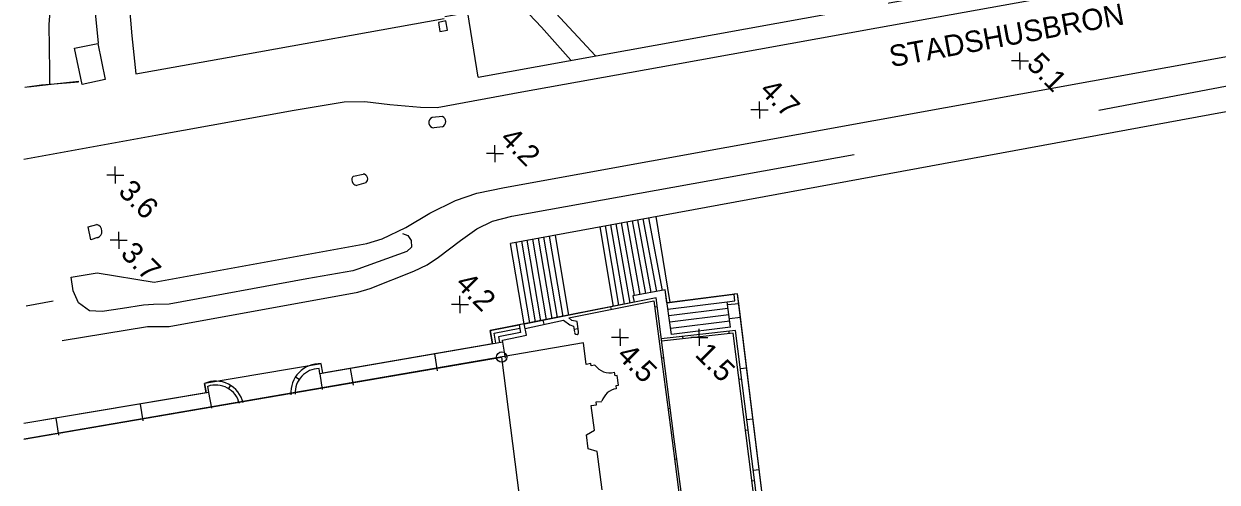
# Model space of a CAD drawing. Extents: x 1596643 to 1597288, y 13057194 to 13057957.
# Drawn here: x 1596648.4 to 1596788, y 13057385.4 to 13057439.2 of the extents above; entities that cross this region are included whole.
import ezdxf

# ---------------------------------------------------------------- set-up
doc = ezdxf.new("R2010")
doc.units = 0
for name, color, linetype in [('BAS bro ej def L', 7, 'Continuous'), ('BAS byggnad anläggning L', 7, 'Continuous'), ('BAS fastighetsgräns samfällighet L', 7, 'Continuous'), ('BAS grind bom låst L', 7, 'Continuous'), ('BAS gränspunkt P', 7, 'Continuous'), ('BAS gång- cykelväg L', 7, 'Continuous'), ('BAS kajkant L', 7, 'Continuous'), ('BAS Level 16', 7, 'Continuous'), ('BAS Level 18', 7, 'Continuous'), ('BAS Level 19', 7, 'Continuous'), ('BAS Level 37', 7, 'Continuous'), ('BAS markytetext T', 7, 'Continuous'), ('BAS trappa L', 7, 'Continuous'), ('BAS väg T', 7, 'Continuous'), ('BAS vägbanekant L', 7, 'Continuous')]:
    doc.layers.add(name, color=color, linetype=linetype)

msp = doc.modelspace()

# ---------------------------------------------------------------- linework, layer by layer
at = {"layer": 'BAS bro ej def L'}
for points in [[(1596701.55, 13057432.92), (1596795.38, 13057449.95), (1596800, 13057453.76)], [(1596705.32, 13057413.45), (1596795.42, 13057430.04)]]:
    msp.add_lwpolyline(points, dxfattribs=at)
at = {"layer": 'BAS byggnad anläggning L'}
for points in [[(1596655.21, 13057432.03), (1596654.31, 13057436.29), (1596657.04, 13057436.86), (1596657.9, 13057432.64), (1596655.21, 13057432.03)], [(1596715.2, 13057399.17), (1596714.76, 13057399.08), (1596714.72, 13057399.34), (1596714.19, 13057399.24), (1596713.86, 13057401.77), (1596648.39, 13057390.49)], [(1596717.71, 13057396.4), (1596717.69, 13057396.78), (1596717.96, 13057396.82), (1596717.82, 13057397.94), (1596717.56, 13057397.9), (1596717.48, 13057398.33)], [(1596716.03, 13057384.55), (1596715.45, 13057389.03), (1596714.4, 13057389.35), (1596714.2, 13057390.98), (1596715.14, 13057391.53), (1596714.78, 13057394.45), (1596715.37, 13057394.51), (1596715.34, 13057394.86), (1596716.01, 13057394.92)]]:
    msp.add_lwpolyline(points, dxfattribs=at)
for centre, radius, start, end in [((1596716.92, 13057400.34), 2.08, 214.1857, 285.4432), ((1596718.1, 13057394.24), 2.2, 100.3328, 161.8867)]:
    msp.add_arc(centre, radius, start, end, dxfattribs=at)
at = {"layer": 'BAS fastighetsgräns samfällighet L'}
for points in [[(1596648.37, 13057390.48), (1596704.28, 13057400.1)], [(1596704.28, 13057400.1), (1596710, 13057355.03)]]:
    msp.add_lwpolyline(points, dxfattribs=at)
at = {"layer": 'BAS grind bom låst L'}
for points in [[(1596722.35, 13057407.04), (1596706.95, 13057403.97)], [(1596730.28, 13057346.49), (1596727.9, 13057364.82), (1596724.49, 13057390.49), (1596722.35, 13057407.04)], [(1596731.57, 13057406.68), (1596731.48, 13057407.43)], [(1596713.27, 13057403.1), (1596713.14, 13057404.29), (1596712.5, 13057404.38), (1596712.16, 13057404.7), (1596722.1, 13057406.69)], [(1596717.13, 13057405.69), (1596717.07, 13057405.99)], [(1596722.1, 13057406.69), (1596724.04, 13057391.87), (1596727.02, 13057368.74), (1596729.92, 13057346.67)], [(1596722.48, 13057405.98), (1596722.2, 13057405.94)], [(1596730.66, 13057406.59), (1596731.57, 13057406.68)], [(1596730.73, 13057406.25), (1596732.03, 13057406.38)], [(1596707.04, 13057403.46), (1596711.51, 13057404.43), (1596712.28, 13057403.88), (1596712.7, 13057403.74), (1596712.83, 13057403.01)], [(1596709.27, 13057403.95), (1596709.16, 13057404.45)], [(1596712.76, 13057403.37), (1596713.2, 13057403.45)], [(1596738.73, 13057345.3), (1596738.55, 13057346.41), (1596737.66, 13057346.82), (1596737.56, 13057347.52), (1596738.54, 13057347.7), (1596735.97, 13057368.27), (1596733.82, 13057386.02), (1596731.64, 13057403.22), (1596722.97, 13057402.24)], [(1596738.43, 13057345.32), (1596738.29, 13057346.21), (1596737.4, 13057346.62), (1596737.23, 13057347.75), (1596738.22, 13057347.94), (1596735.69, 13057368.23), (1596733.54, 13057385.98), (1596731.39, 13057402.9), (1596723, 13057401.96)], [(1596730.86, 13057403.13), (1596730.89, 13057402.84)], [(1596725.44, 13057402.52), (1596725.48, 13057402.23)], [(1596723.26, 13057400.03), (1596722.98, 13057399.99)], [(1596683, 13057398.15), (1596682.92, 13057398.75)], [(1596683.35, 13057398.22), (1596683.16, 13057399.33)], [(1596680.16, 13057397.78), (1596680.6, 13057397.5)], [(1596732.37, 13057397.5), (1596732.08, 13057397.46)], [(1596669.72, 13057395.9), (1596669.51, 13057397.01)], [(1596670.03, 13057395.95), (1596669.9, 13057396.68)], [(1596672.56, 13057396.8), (1596672.32, 13057396.41)], [(1596724.03, 13057394.08), (1596723.75, 13057394.04)], [(1596733.12, 13057391.55), (1596732.84, 13057391.51)], [(1596724.81, 13057388.13), (1596724.52, 13057388.09)], [(1596733.88, 13057385.59), (1596733.59, 13057385.56)]]:
    msp.add_lwpolyline(points, dxfattribs=at)
for centre, radius, start, end in [((1596713.06, 13057402.99), 0.231, 176.5167, 26.4542), ((1596683.01, 13057395.95), 3.39, 87.5127, 184.3844), ((1596682.93, 13057395.95), 2.8, 90.3272, 183.6006), ((1596670.83, 13057394.01), 3.28, 12.7749, 113.6683), ((1596670.82, 13057393.97), 2.86, 13.9294, 108.7325)]:
    msp.add_arc(centre, radius, start, end, dxfattribs=at)
at = {"layer": 'BAS gränspunkt P'}
for centre, radius in [((1596704.29, 13057400.11), 0.6), ((1596704.29, 13057400.11), 0.6), ((1596704.28, 13057400.1), 0.001), ((1596704.28, 13057400.1), 0.001)]:
    msp.add_circle(centre, radius, dxfattribs=at)
at = {"layer": 'BAS gång- cykelväg L'}
for points in [[(1596660.57, 13057459.15), (1596659.29, 13057457.99), (1596661.01, 13057437.74)], [(1596685.78, 13057459.15), (1596689.24, 13057455.42), (1596692.23, 13057452.24), (1596694.09, 13057450.42), (1596694.74, 13057449.91), (1596695.2, 13057449.63), (1596696.08, 13057449.26), (1596696.88, 13057448.94), (1596698.08, 13057448.55), (1596698.88, 13057448.29), (1596699.97, 13057447.87), (1596701.53, 13057446.75), (1596705.35, 13057442.6), (1596708.96, 13057438.78), (1596712.4, 13057434.89)], [(1596657.09, 13057436.87), (1596655.2, 13057456.14)]]:
    msp.add_lwpolyline(points, dxfattribs=at)
at = {"layer": 'BAS kajkant L'}
for points in [[(1596715.28, 13057435.41), (1596704.96, 13057446.53), (1596696.4, 13057455.7), (1596693.3, 13057459.15)], [(1596732.03, 13057406.38), (1596731.89, 13057407.51), (1596731.48, 13057407.46)], [(1596739.64, 13057345.22), (1596737.13, 13057365.02), (1596732.03, 13057406.38)], [(1596732.23, 13057404.76), (1596730.94, 13057404.6)], [(1596732.96, 13057398.8), (1596732.21, 13057398.71)], [(1596733.7, 13057392.85), (1596732.97, 13057392.76)], [(1596734.43, 13057386.89), (1596733.72, 13057386.81)]]:
    msp.add_lwpolyline(points, dxfattribs=at)
at = {"layer": 'BAS Level 16'}
for p, q in [((1596764.94, 13057434.8), (1596763.94, 13057434.8)), ((1596764.94, 13057434.8), (1596763.94, 13057434.8)), ((1596764.94, 13057434.8), (1596764.94, 13057435.8)), ((1596764.94, 13057434.8), (1596764.94, 13057435.8)), ((1596764.94, 13057434.8), (1596765.94, 13057434.8)), ((1596764.94, 13057434.8), (1596764.94, 13057433.8)), ((1596764.94, 13057434.8), (1596765.94, 13057434.8)), ((1596764.94, 13057434.8), (1596764.94, 13057433.8)), ((1596734.46, 13057429.07), (1596734.46, 13057430.07)), ((1596734.46, 13057429.07), (1596734.46, 13057430.07)), ((1596734.46, 13057429.07), (1596733.46, 13057429.07)), ((1596734.46, 13057429.07), (1596733.46, 13057429.07)), ((1596734.46, 13057429.07), (1596735.46, 13057429.07)), ((1596734.46, 13057429.07), (1596734.46, 13057428.07)), ((1596734.46, 13057429.07), (1596735.46, 13057429.07)), ((1596734.46, 13057429.07), (1596734.46, 13057428.07)), ((1596703.5, 13057423.95), (1596702.5, 13057423.95)), ((1596703.5, 13057423.95), (1596702.5, 13057423.95)), ((1596703.5, 13057423.95), (1596703.5, 13057424.95)), ((1596703.5, 13057423.95), (1596703.5, 13057424.95)), ((1596703.5, 13057423.95), (1596704.5, 13057423.95)), ((1596703.5, 13057423.95), (1596703.5, 13057422.95)), ((1596703.5, 13057423.95), (1596704.5, 13057423.95)), ((1596703.5, 13057423.95), (1596703.5, 13057422.95)), ((1596659.07, 13057421.44), (1596659.07, 13057422.44)), ((1596659.07, 13057421.44), (1596659.07, 13057422.44)), ((1596659.07, 13057421.44), (1596658.07, 13057421.44)), ((1596659.07, 13057421.44), (1596658.07, 13057421.44)), ((1596659.07, 13057421.44), (1596660.07, 13057421.44)), ((1596659.07, 13057421.44), (1596659.07, 13057420.44)), ((1596659.07, 13057421.44), (1596660.07, 13057421.44)), ((1596659.07, 13057421.44), (1596659.07, 13057420.44)), ((1596659.47, 13057413.79), (1596659.47, 13057414.79)), ((1596659.47, 13057413.79), (1596659.47, 13057414.79)), ((1596659.47, 13057413.79), (1596658.47, 13057413.79)), ((1596659.47, 13057413.79), (1596658.47, 13057413.79)), ((1596659.47, 13057413.79), (1596660.47, 13057413.79)), ((1596659.47, 13057413.79), (1596659.47, 13057412.79)), ((1596659.47, 13057413.79), (1596660.47, 13057413.79)), ((1596659.47, 13057413.79), (1596659.47, 13057412.79)), ((1596699.4, 13057406.27), (1596699.4, 13057407.27)), ((1596699.4, 13057406.27), (1596699.4, 13057407.27)), ((1596699.4, 13057406.27), (1596698.4, 13057406.27)), ((1596699.4, 13057406.27), (1596698.4, 13057406.27)), ((1596699.4, 13057406.27), (1596700.4, 13057406.27)), ((1596699.4, 13057406.27), (1596699.4, 13057405.27)), ((1596699.4, 13057406.27), (1596700.4, 13057406.27)), ((1596699.4, 13057406.27), (1596699.4, 13057405.27)), ((1596718.14, 13057402.41), (1596718.14, 13057403.41)), ((1596718.14, 13057402.41), (1596718.14, 13057403.41)), ((1596727.41, 13057402.41), (1596727.41, 13057403.41)), ((1596727.41, 13057402.41), (1596727.41, 13057403.41)), ((1596718.14, 13057402.41), (1596717.14, 13057402.41)), ((1596718.14, 13057402.41), (1596717.14, 13057402.41)), ((1596718.14, 13057402.41), (1596719.14, 13057402.41)), ((1596718.14, 13057402.41), (1596718.14, 13057401.41)), ((1596718.14, 13057402.41), (1596719.14, 13057402.41)), ((1596718.14, 13057402.41), (1596718.14, 13057401.41)), ((1596727.41, 13057402.41), (1596726.41, 13057402.41)), ((1596727.41, 13057402.41), (1596726.41, 13057402.41)), ((1596727.41, 13057402.41), (1596728.41, 13057402.41)), ((1596727.41, 13057402.41), (1596727.41, 13057401.41)), ((1596727.41, 13057402.41), (1596728.41, 13057402.41)), ((1596727.41, 13057402.41), (1596727.41, 13057401.41))]:
    msp.add_line(p, q, dxfattribs=at)
at = {"layer": 'BAS Level 18'}
for p, q in [((1596696.79, 13057398.51), (1596696.45, 13057400.48)), ((1596696.79, 13057398.51), (1596696.45, 13057400.48)), ((1596686.94, 13057396.81), (1596686.6, 13057398.78)), ((1596686.94, 13057396.81), (1596686.6, 13057398.78)), ((1596662.34, 13057392.63), (1596662.01, 13057394.6)), ((1596662.34, 13057392.63), (1596662.01, 13057394.6)), ((1596652.48, 13057390.97), (1596652.15, 13057392.95)), ((1596652.48, 13057390.97), (1596652.15, 13057392.95))]:
    msp.add_line(p, q, dxfattribs=at)
for points in [[(1596697.94, 13057438.4), (1596697.74, 13057439.5), (1596696.88, 13057439.32), (1596697.05, 13057438.25), (1596697.94, 13057438.4)], [(1596724.18, 13057402.75), (1596723.41, 13057407.98), (1596719.65, 13057407.27), (1596719.81, 13057406.54)], [(1596704.74, 13057399.99), (1596704.42, 13057401.87), (1596683, 13057398.15), (1596683.3, 13057396.32)], [(1596670.38, 13057394.11), (1596670.03, 13057395.95), (1596648.37, 13057392.31)]]:
    msp.add_lwpolyline(points, dxfattribs=at)
at = {"layer": 'BAS Level 19'}
msp.add_lwpolyline([(1596701.55, 13057432.92), (1596700.33, 13057440.46), (1596697.62, 13057439.96)], dxfattribs=at)
at = {"layer": 'BAS Level 37'}
for points in [[(1596723.41, 13057407.98), (1596719.65, 13057407.27)], [(1596719.65, 13057407.27), (1596719.81, 13057406.54)], [(1596723.63, 13057406.47), (1596723.41, 13057407.98)], [(1596731.89, 13057407.51), (1596723.63, 13057406.47)], [(1596739.57, 13057345.15), (1596731.89, 13057407.51)], [(1596719.81, 13057406.54), (1596702.94, 13057403.24)], [(1596702.94, 13057403.24), (1596703.22, 13057401.66)], [(1596703.22, 13057401.66), (1596683.35, 13057398.22)], [(1596683.16, 13057399.33), (1596669.51, 13057397.01)], [(1596683.35, 13057398.22), (1596683.16, 13057399.33)], [(1596669.72, 13057395.9), (1596648.37, 13057392.31)], [(1596669.51, 13057397.01), (1596669.72, 13057395.9)]]:
    msp.add_lwpolyline(points, dxfattribs=at)
at = {"layer": 'BAS trappa L'}
for points in [[(1596717.36, 13057406.05), (1596715.81, 13057415.38)], [(1596718.01, 13057406.18), (1596716.44, 13057415.5)], [(1596718.66, 13057406.31), (1596717.07, 13057415.61)], [(1596719.31, 13057406.44), (1596717.7, 13057415.73)], [(1596719.84, 13057407.31), (1596718.33, 13057415.84)], [(1596720.49, 13057407.43), (1596718.96, 13057415.96)], [(1596721.14, 13057407.55), (1596719.59, 13057416.08)], [(1596721.79, 13057407.68), (1596720.22, 13057416.19)], [(1596722.44, 13057407.8), (1596720.85, 13057416.31)], [(1596721.48, 13057416.42), (1596723.09, 13057407.92)], [(1596722.31, 13057416.58), (1596723.98, 13057406.51)], [(1596709.53, 13057404.48), (1596707.93, 13057413.91)], [(1596710.18, 13057404.61), (1596708.58, 13057414.03)], [(1596710.83, 13057404.74), (1596709.23, 13057414.16)], [(1596711.47, 13057404.86), (1596709.89, 13057414.28)], [(1596710.54, 13057414.4), (1596712.12, 13057404.99)], [(1596706.94, 13057404), (1596705.32, 13057413.42)], [(1596707.59, 13057404.1), (1596705.97, 13057413.54)], [(1596708.24, 13057404.23), (1596706.63, 13057413.67)], [(1596708.89, 13057404.36), (1596707.28, 13057413.79)], [(1596723.63, 13057406.47), (1596731.48, 13057407.46)], [(1596723.74, 13057405.73), (1596730.66, 13057406.59)], [(1596723.85, 13057404.98), (1596730.77, 13057405.85)], [(1596731.08, 13057403.6), (1596730.67, 13057406.58)], [(1596723.96, 13057404.24), (1596730.87, 13057405.1)], [(1596724.07, 13057403.5), (1596730.97, 13057404.35)], [(1596703.22, 13057401.66), (1596702.94, 13057403.24), (1596706.35, 13057403.89)], [(1596703.61, 13057401.72), (1596703.4, 13057402.92), (1596706.42, 13057403.5)], [(1596704.42, 13057401.87), (1596704.39, 13057402.08), (1596707.18, 13057402.66), (1596706.94, 13057404), (1596706.33, 13057403.89), (1596706.49, 13057402.99), (1596703.91, 13057402.47), (1596704.04, 13057401.8)], [(1596731.08, 13057403.6), (1596724.18, 13057402.75)]]:
    msp.add_lwpolyline(points, dxfattribs=at)
at = {"layer": 'BAS vägbanekant L'}
for points in [[(1596652.06, 13057455.97), (1596652.01, 13057451.81), (1596651.83, 13057446.86), (1596651.66, 13057443.61), (1596651.3, 13057439.08), (1596651.36, 13057433.62), (1596651.38, 13057432.1)], [(1596648.37, 13057423.28), (1596663.82, 13057426.1), (1596679.99, 13057429.02), (1596685.87, 13057430.02), (1596688.26, 13057430.05), (1596691.2, 13057429.7), (1596694.78, 13057429.39), (1596696.75, 13057429.34), (1596706.65, 13057431.17), (1596724.24, 13057434.34), (1596748.19, 13057438.67), (1596774.7, 13057443.5), (1596786.95, 13057445.68), (1596794.41, 13057447.06), (1596798.34, 13057447.86)], [(1596661.01, 13057437.74), (1596661.48, 13057433.31), (1596672.41, 13057435.25), (1596697.57, 13057439.77)], [(1596692.7, 13057414.57), (1596693.31, 13057414.35), (1596693.7, 13057413.76), (1596693.75, 13057413), (1596693.2, 13057412.47), (1596687.46, 13057410.39), (1596686.89, 13057410.21), (1596681.47, 13057409.28), (1596665.38, 13057406.3), (1596663.54, 13057406.25), (1596662.37, 13057406.18), (1596659.92, 13057405.81), (1596657.54, 13057405.46), (1596656.05, 13057405.53), (1596654.78, 13057406.46), (1596654.14, 13057407.87), (1596653.89, 13057409.46), (1596656.96, 13057409.97), (1596663.64, 13057408.88), (1596688.52, 13057413.4), (1596690.32, 13057413.96), (1596693.06, 13057415.3), (1596695.9, 13057416.97), (1596698.88, 13057418.47), (1596701.4, 13057419.3), (1596704.62, 13057419.96), (1596799.46, 13057437.21)], [(1596654.75, 13057432.33), (1596651.47, 13057432.04), (1596650.44, 13057431.97), (1596648.5, 13057431.71)], [(1596654.82, 13057432.38), (1596651.56, 13057432.05), (1596648.86, 13057431.74)], [(1596794.96, 13057432.93), (1596774.16, 13057429.01)], [(1596697.37, 13057428.3), (1596696.17, 13057428.18)], [(1596697.36, 13057427.1), (1596696.37, 13057426.97)], [(1596652.86, 13057402.04), (1596662.86, 13057403.69), (1596664.36, 13057403.68), (1596665.38, 13057403.69), (1596687.46, 13057407.7), (1596688.91, 13057408.15), (1596694.02, 13057410.17), (1596695.58, 13057410.9), (1596696.89, 13057411.8), (1596699.47, 13057413.78), (1596701.38, 13057415.12), (1596703.22, 13057416.03), (1596705.49, 13057416.62), (1596745.53, 13057423.84)], [(1596686.95, 13057421.32), (1596688.07, 13057421.55)], [(1596688.39, 13057420.53), (1596687.29, 13057420.22)], [(1596657, 13057414.1), (1596656.21, 13057413.86), (1596655.9, 13057415.38), (1596656.91, 13057415.64)], [(1596648.63, 13057406.1), (1596651.82, 13057406.68)]]:
    msp.add_lwpolyline(points, dxfattribs=at)
for centre, radius, start, end in [((1596696.37, 13057427.59), 0.622, 109.0466, 269.6315), ((1596697.1, 13057427.7), 0.654, 293.4742, 66.0998), ((1596687.38, 13057420.85), 0.635, 132.516, 262.0358), ((1596688.06, 13057420.99), 0.562, 306.0349, 89.0825), ((1596656.7, 13057414.85), 0.814, 291.2651, 75.1275)]:
    msp.add_arc(centre, radius, start, end, dxfattribs=at)

# ---------------------------------------------------------------- texts
at = {"layer": 'BAS markytetext T'}
for s, p in [('5.1', (1596765.59, 13057434.27)), ('4.7', (1596734.35, 13057431.22)), ('4.2', (1596703.97, 13057425.55)), ('3.6', (1596659.3, 13057419.37)), ('3.7', (1596659.57, 13057412.1)), ('4.2', (1596698.76, 13057408.56)), ('1.5', (1596726.79, 13057400.29)), ('4.5', (1596717.65, 13057400.18))]:
    msp.add_text(s, height=2.5, rotation=315, dxfattribs=at).set_placement(p)
at = {"layer": 'BAS väg T'}
msp.add_text('STADSHUSBRON', height=2.5, rotation=10.431, dxfattribs=at).set_placement((1596749.89, 13057434.07))

doc.saveas('drawing.dxf')
